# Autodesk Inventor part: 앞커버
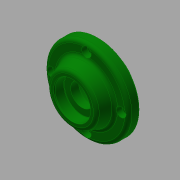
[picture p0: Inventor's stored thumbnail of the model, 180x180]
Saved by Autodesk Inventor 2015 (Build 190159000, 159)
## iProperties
Created: 2017-08
Part Number: 앞커버
Material: 알루미늄 6061
Document SubType Name: Modeling
Designer: mduedu
Density: 2.71 g/cm^3
Appearance: 진녹색
Mass: 119.316 g
Surface Area: 145.143 cm^2
Volume: 44.0282 cm^3
Author: mduedu
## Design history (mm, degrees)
sketch "스케치1"
  geometry: C1 r 35 at (0, 0); 1 further point
  constraints: 1 centre point, 1 coincident
  dimensions: "d0" = 70 diameter of C1
extrude "돌출1" new body sketch "스케치1" distance "d1" = 10; taper "d2" = 0 deg
sketch "스케치2"
  geometry: C1 r 24 at (0, 0); 1 further point
  constraints: 1 centre point, 1 coincident
  dimensions: "d3" = 48 diameter of C1
node "작업 평면1"
sketch "스케치3"
  geometry: C1 r 20 at (0, 0); 1 further point
  constraints: 1 centre point, 1 coincident
  dimensions: "d5" = 40 diameter of C1
feature "로프트1" sketch "스케치3" dims "d6" = 0, "d7" = 90 deg, "d8" = 0, "d9" = 90 deg
sketch "스케치4"
  geometry: C1 r 24 at (0, 0) reference; 1 further point
extrude "돌출2" join sketch "스케치4" distance "d10" = 8; taper "d11" = 0 deg
hole "구멍1" diameter "d14" = 40; stored, may be unused: countersink angle "d18" = 90 deg, drill point angle "d20" = 0 deg; dims "d12" = 10, "d13" = 10, "d15" = 6, "d16" = 4, "d17" = 2, "d19" = 12
hole "구멍2" diameter "d23" = 34; stored, may be unused: countersink angle "d27" = 90 deg, drill point angle "d29" = 0 deg; dims "d21" = 10, "d22" = 10, "d24" = 6, "d25" = 4, "d26" = 2, "d28" = 3
hole "구멍3" diameter "d32" = 19; stored, may be unused: countersink angle "d36" = 90 deg, drill point angle "d38" = 0 deg; dims "d30" = 10, "d31" = 10, "d33" = 6, "d34" = 4, "d35" = 2, "d37" = 3
chamfer "모따기1" distance "d39" = 1; stored, may be unused: second distance "d40" = 2, angle "d41" = 45 deg
sketch "스케치5"
  geometry: C1 r 15 at (0, 0); 1 further point
  constraints: 1 centre point, 1 coincident
  dimensions: "d42" = 30 diameter of C1
extrude "돌출3" cut sketch "스케치5" distance "d43" = 8.3; taper "d44" = 0 deg
chamfer "모따기2" distance "d47" = 0.8; stored, may be unused: second distance "d48" = 2, angle "d49" = 30 deg
fillet "모깎기1" dims "d50" = 0.3
fillet "모깎기2" dims "d51" = 0.3
fillet "모깎기3" dims "d52" = 3
sketch "스케치6" dims "d53" = 58
  geometry: 6 further points
  constraints: 2 vertical alignment, 1 coincident, 7 other
  dimensions: "d56" = 360 deg dimension on point (0, 0) point (0, 29) (derived)
sketch "스케치9"
  geometry: 4 further points
  constraints: 4 other
hole "구멍6" sketch "스케치9" at (-29, 0), (0, -29), (29, 0), (0, 29) diameter "d72" = 4.5; stored, may be unused: countersink angle "d76" = 90 deg, drill point angle "d78" = 0 deg; dims "d73" = 6, "d74" = 8, "d75" = 4.6, "d77" = 8
fillet "모깎기4" dims "d79" = 3
fillet "모깎기5" dims "d80" = 3
fillet "모깎기6" dims "d81" = 3
chamfer "모따기3" distance "d82" = 1; stored, may be unused: second distance "d83" = 2, angle "d84" = 30 deg
node "솔리드1"
other parameters: "d4" = 12
